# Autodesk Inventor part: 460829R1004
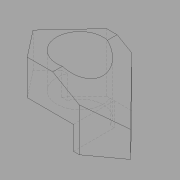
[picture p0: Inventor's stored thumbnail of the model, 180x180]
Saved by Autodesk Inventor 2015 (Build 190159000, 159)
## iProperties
Created: 2016-08
Part Number: 460829R1004
Material: 일반
Document SubType Name: Modeling
Designer: jio
Density: 1 g/cm^3
Appearance: 기본값
Author: jio
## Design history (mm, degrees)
sketch "스케치1"
  geometry: L1 (-9.387, 55)-(34, 55); L2 (34, 55)-(104.673, -18.184); L3 (104.673, -18.184)-(54, -55); L4 (54, -55)-(-34.842, -55); L5 (-34.842, -55)-(-70, -10); L6 (-70, -10)-(-9.387, 55); C1 r 39.5 at (0, 0); 1 further point
  constraints: 12 end point, 1 centre point, 1 coincident, 1 horizontal, 1 parallel
  dimensions: "d0" = 79 diameter of C1; "d2" = 134 deg angle of L2 L1; "d3" = 144 deg angle of L3 L4; "d4" = 128 deg angle of L4 L5; "d5" = 99 deg angle of L5 L6; "d6" = 110 vertical distance of L4.end L1.start; "d7" = 124 horizontal distance of L3.end L5.end; "d8" = 104 horizontal distance of L1.end L5.end; "d9" = 45 vertical distance of L4.end L5.end; "d10" = 55 distance from line of L4 point (0, 0); "d11" = 70 horizontal distance of point (0, 0) L5.end
extrude "돌출1" new body sketch "스케치1" distance "d12" = 100; taper "d13" = 0 deg
sketch "스케치2"
  geometry: L1 (43.515, 100)-(139.515, 100); L2 (139.515, 100)-(139.515, 44.574); L3 (139.515, 44.574)-(43.515, 100); 2 further points
  constraints: 6 end point, 1 coincident, 1 horizontal, 1 perpendicular
  dimensions: "d14" = 30 deg angle of L3 L1; "d15" = 96 distance of L1.start L1.end
extrude "돌출2" cut sketch "스케치2" stored distance "d16" = 100; taper "d17" = 0 deg
sketch "스케치3"
  geometry: L1 (-35.158, 40)-(78.842, 40); L2 (78.842, 40)-(78.842, 0); L3 (78.842, 0)-(-35.158, 0); L4 (-35.158, 0)-(-35.158, 40); 2 further points
  constraints: 8 end point, 2 parallel, 1 coincident, 1 horizontal, 1 perpendicular
  dimensions: "d18" = 40 distance of L3.end L1.start; "d19" = 114 distance between parallel lines of L2 L4
extrude "돌출3" cut sketch "스케치3" distance "d20" = 70; taper "d21" = 0 deg
node "솔리드1"
